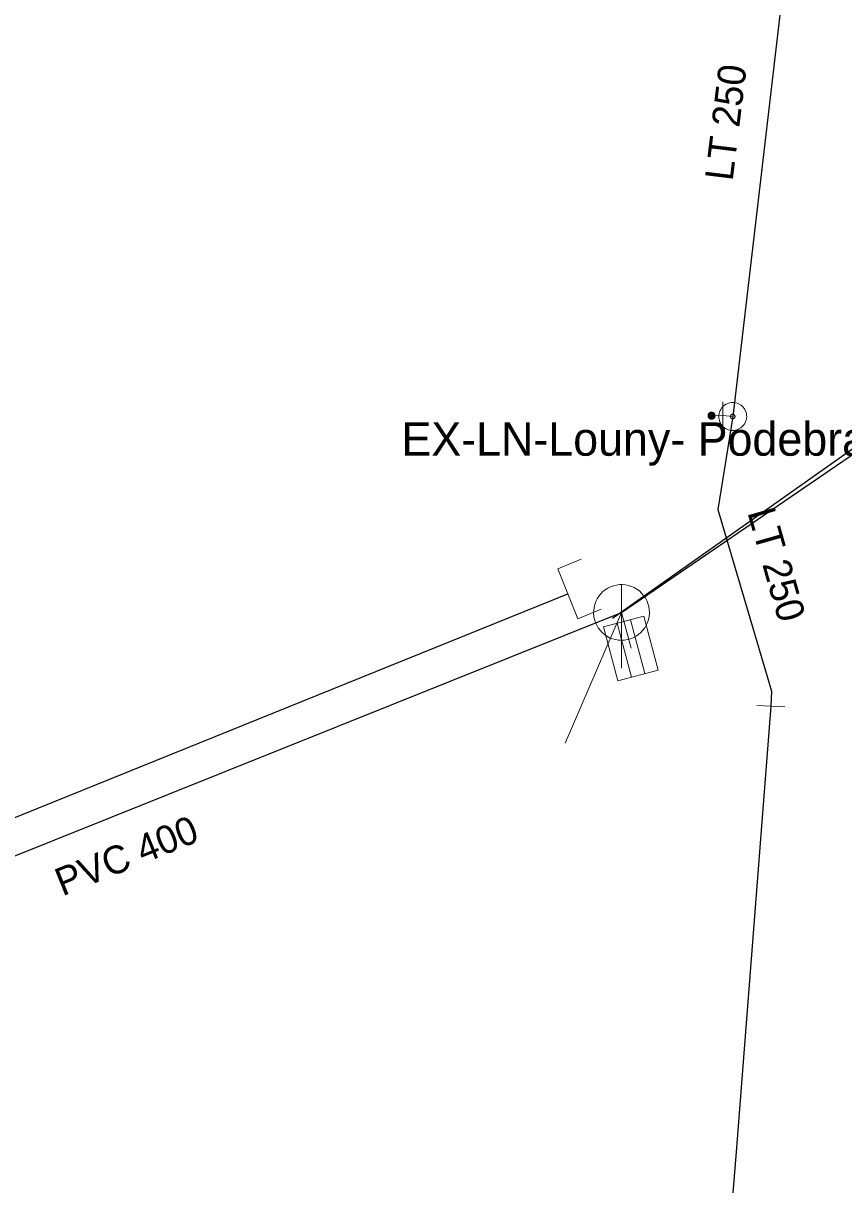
# Model space of a CAD drawing. Extents: x -783064 to -782702, y -1007904 to -1007145.
# Drawn here: x -782854.89 to -782825.5, y -1007838.15 to -1007796.52 of the extents above; entities that cross this region are included whole.
import ezdxf

# ---------------------------------------------------------------- set-up
doc = ezdxf.new("R2010")
doc.units = 0
doc.header["$LTSCALE"] = 0.4
for name, color, linetype, lineweight in [('1', 7, 'Continuous', 13), ('11', 7, 'Continuous', 13), ('14', 7, 'Continuous', 13), ('17', 7, 'Continuous', 25), ('22', 7, 'Continuous', 13), ('34', 7, 'Continuous', 13), ('42', 7, 'Continuous', 13), ('47', 7, 'Continuous', 13), ('9', 7, 'Continuous', 13)]:
    doc.layers.add(name, color=color, linetype=linetype, lineweight=lineweight)

msp = doc.modelspace()

# ---------------------------------------------------------------- linework, layer by layer
at = {"layer": '11'}
for p in [(-782835.48, -1007822.322), (-782833.12, -1007818.92)]:
    msp.add_line(p, (-782833.46, -1007817.64), dxfattribs=at)
at = {"layer": '14', "lineweight": 25}
for p, q in [((-782833.78, -1007817.85), (-782810.509, -1007801.396)), ((-782868.51, -1007831.71), (-782833.46, -1007817.64))]:
    msp.add_line(p, q, dxfattribs=at)
at = {"layer": '14'}
for p, q in [((-782829.833, -1007810.587), (-782830.234, -1007810.588)), ((-782829.476, -1007810.618), (-782829.833, -1007810.587))]:
    msp.add_line(p, q, dxfattribs=at)
at = {"layer": '14', "lineweight": 25}
msp.add_lwpolyline([(-782833.46, -1007817.64), (-782817.57, -1007806.77), (-782809.98, -1007801.58)], dxfattribs=at)
at = {"layer": '17'}
for points in [[(-782826.82, -1007787.241), (-782826.831, -1007787.709), (-782826.833, -1007788.054), (-782829.476, -1007810.618)], [(-782829.476, -1007810.618), (-782830.015, -1007813.952), (-782828.09, -1007820.465), (-782828.114, -1007821.004)], [(-783063.843, -1007879.786), (-783019.96, -1007877.952), (-783013.339, -1007877.559), (-782960.98, -1007867.795), (-782835.384, -1007816.97)], [(-782828.114, -1007821.004), (-782829.348, -1007836.974), (-782830.594, -1007852.256), (-782831.989, -1007872.135), (-782832.224, -1007875.397)]]:
    msp.add_lwpolyline(points, dxfattribs=at)
at = {"layer": '22'}
for p, q in [((-782833.46, -1007819.64), (-782833.459, -1007816.64)), ((-782833.108, -1007819.962), (-782833.621, -1007818.029)), ((-782832.625, -1007819.834), (-782833.138, -1007817.901))]:
    msp.add_line(p, q, dxfattribs=at)
for points in [[(-782832.46, -1007817.64), (-782832.465, -1007817.531), (-782832.483, -1007817.423), (-782832.513, -1007817.317), (-782832.553, -1007817.216), (-782832.605, -1007817.119), (-782832.667, -1007817.029), (-782832.739, -1007816.946), (-782832.819, -1007816.872), (-782832.907, -1007816.806), (-782833.001, -1007816.751), (-782833.101, -1007816.706), (-782833.206, -1007816.673), (-782833.313, -1007816.651), (-782833.422, -1007816.641), (-782833.532, -1007816.643), (-782833.64, -1007816.657), (-782833.747, -1007816.682), (-782833.85, -1007816.719), (-782833.948, -1007816.768), (-782834.04, -1007816.826), (-782834.126, -1007816.895), (-782834.203, -1007816.972), (-782834.272, -1007817.058), (-782834.331, -1007817.15), (-782834.379, -1007817.248), (-782834.416, -1007817.351), (-782834.442, -1007817.458), (-782834.456, -1007817.566), (-782834.459, -1007817.676), (-782834.449, -1007817.785), (-782834.428, -1007817.892), (-782834.394, -1007817.996), (-782834.35, -1007818.096), (-782834.295, -1007818.191), (-782834.229, -1007818.279), (-782834.155, -1007818.359), (-782834.072, -1007818.431), (-782833.982, -1007818.493), (-782833.886, -1007818.545), (-782833.784, -1007818.586), (-782833.679, -1007818.616), (-782833.571, -1007818.634), (-782833.461, -1007818.64), (-782833.352, -1007818.634), (-782833.244, -1007818.616), (-782833.139, -1007818.587), (-782833.037, -1007818.546), (-782832.94, -1007818.494), (-782832.85, -1007818.432), (-782832.767, -1007818.361), (-782832.692, -1007818.281), (-782832.627, -1007818.193), (-782832.571, -1007818.099), (-782832.527, -1007817.999), (-782832.493, -1007817.895), (-782832.471, -1007817.787), (-782832.461, -1007817.678)], [(-782833.591, -1007820.091), (-782834.105, -1007818.158), (-782832.655, -1007817.773), (-782832.141, -1007819.706)]]:
    msp.add_lwpolyline(points, close=True, dxfattribs=at)
at = {"layer": '34'}
for p, q in [((-782829.831, -1007811.086), (-782829.833, -1007810.087)), ((-782827.614, -1007821.025), (-782828.613, -1007820.981))]:
    msp.add_line(p, q, dxfattribs=at)
at = {"layer": '42'}
msp.add_lwpolyline([(-782834.911, -1007815.736), (-782835.746, -1007816.074), (-782835.022, -1007817.865), (-782834.186, -1007817.527)], dxfattribs=at)
at = {"layer": '47'}
for points in [[(-782829.534, -1007811.114), (-782829.482, -1007811.117), (-782829.429, -1007811.115), (-782829.378, -1007811.107), (-782829.327, -1007811.095), (-782829.278, -1007811.077), (-782829.23, -1007811.053), (-782829.187, -1007811.025), (-782829.146, -1007810.992), (-782829.108, -1007810.957), (-782829.075, -1007810.916), (-782829.045, -1007810.872), (-782829.022, -1007810.826), (-782829.002, -1007810.778), (-782828.988, -1007810.727), (-782828.979, -1007810.676), (-782828.976, -1007810.624), (-782828.978, -1007810.571), (-782828.986, -1007810.519), (-782828.998, -1007810.469), (-782829.016, -1007810.42), (-782829.04, -1007810.372), (-782829.068, -1007810.328), (-782829.1, -1007810.287), (-782829.136, -1007810.249), (-782829.177, -1007810.217), (-782829.221, -1007810.187), (-782829.267, -1007810.163), (-782829.315, -1007810.144), (-782829.366, -1007810.13), (-782829.417, -1007810.121), (-782829.469, -1007810.118), (-782829.522, -1007810.12), (-782829.574, -1007810.127), (-782829.624, -1007810.14), (-782829.673, -1007810.158), (-782829.72, -1007810.181), (-782829.765, -1007810.209), (-782829.806, -1007810.241), (-782829.844, -1007810.278), (-782829.876, -1007810.319), (-782829.906, -1007810.363), (-782829.93, -1007810.408), (-782829.949, -1007810.457), (-782829.963, -1007810.508), (-782829.972, -1007810.559), (-782829.975, -1007810.611), (-782829.973, -1007810.664), (-782829.966, -1007810.715), (-782829.953, -1007810.766), (-782829.935, -1007810.815), (-782829.912, -1007810.862), (-782829.884, -1007810.906), (-782829.851, -1007810.947), (-782829.815, -1007810.985), (-782829.774, -1007811.018), (-782829.73, -1007811.048), (-782829.685, -1007811.071), (-782829.636, -1007811.091), (-782829.585, -1007811.105)], [(-782829.485, -1007810.699), (-782829.476, -1007810.7), (-782829.468, -1007810.699), (-782829.46, -1007810.698), (-782829.451, -1007810.696), (-782829.443, -1007810.693), (-782829.436, -1007810.689), (-782829.428, -1007810.684), (-782829.421, -1007810.679), (-782829.416, -1007810.673), (-782829.41, -1007810.666), (-782829.405, -1007810.659), (-782829.401, -1007810.651), (-782829.398, -1007810.644), (-782829.395, -1007810.636), (-782829.394, -1007810.627), (-782829.393, -1007810.618), (-782829.394, -1007810.61), (-782829.395, -1007810.602), (-782829.397, -1007810.593), (-782829.4, -1007810.585), (-782829.404, -1007810.578), (-782829.409, -1007810.57), (-782829.414, -1007810.563), (-782829.42, -1007810.557), (-782829.427, -1007810.552), (-782829.434, -1007810.547), (-782829.442, -1007810.543), (-782829.449, -1007810.54), (-782829.457, -1007810.537), (-782829.466, -1007810.536), (-782829.475, -1007810.535), (-782829.483, -1007810.536), (-782829.491, -1007810.537), (-782829.5, -1007810.539), (-782829.508, -1007810.542), (-782829.515, -1007810.545), (-782829.523, -1007810.551), (-782829.53, -1007810.556), (-782829.536, -1007810.562), (-782829.541, -1007810.569), (-782829.546, -1007810.576), (-782829.55, -1007810.584), (-782829.553, -1007810.591), (-782829.556, -1007810.599), (-782829.557, -1007810.608), (-782829.558, -1007810.617), (-782829.557, -1007810.625), (-782829.556, -1007810.633), (-782829.554, -1007810.642), (-782829.551, -1007810.65), (-782829.548, -1007810.657), (-782829.542, -1007810.665), (-782829.537, -1007810.672), (-782829.531, -1007810.677), (-782829.524, -1007810.683), (-782829.517, -1007810.688), (-782829.509, -1007810.692), (-782829.502, -1007810.695), (-782829.494, -1007810.698)]]:
    msp.add_lwpolyline(points, close=True, dxfattribs=at)
at = {"layer": '9'}
for points in [[(-782830.36, -1007810.588), (-782830.36, -1007810.601), (-782830.358, -1007810.614), (-782830.355, -1007810.627), (-782830.35, -1007810.639), (-782830.344, -1007810.651), (-782830.337, -1007810.662), (-782830.329, -1007810.672), (-782830.319, -1007810.682), (-782830.309, -1007810.69), (-782830.298, -1007810.697), (-782830.286, -1007810.703), (-782830.274, -1007810.708), (-782830.261, -1007810.711), (-782830.248, -1007810.713), (-782830.235, -1007810.715), (-782830.222, -1007810.714), (-782830.209, -1007810.712), (-782830.196, -1007810.709), (-782830.184, -1007810.704), (-782830.172, -1007810.698), (-782830.161, -1007810.691), (-782830.151, -1007810.683), (-782830.141, -1007810.673), (-782830.133, -1007810.663), (-782830.126, -1007810.652), (-782830.12, -1007810.64), (-782830.115, -1007810.628), (-782830.112, -1007810.615), (-782830.11, -1007810.602), (-782830.108, -1007810.589), (-782830.109, -1007810.576), (-782830.111, -1007810.563), (-782830.114, -1007810.55), (-782830.119, -1007810.538), (-782830.125, -1007810.526), (-782830.132, -1007810.515), (-782830.14, -1007810.505), (-782830.15, -1007810.495), (-782830.16, -1007810.487), (-782830.171, -1007810.48), (-782830.183, -1007810.474), (-782830.195, -1007810.469), (-782830.208, -1007810.466), (-782830.221, -1007810.464), (-782830.234, -1007810.463), (-782830.247, -1007810.463), (-782830.26, -1007810.465), (-782830.273, -1007810.468), (-782830.285, -1007810.473), (-782830.297, -1007810.479), (-782830.308, -1007810.486), (-782830.318, -1007810.494), (-782830.328, -1007810.504), (-782830.336, -1007810.514), (-782830.343, -1007810.525), (-782830.349, -1007810.537), (-782830.354, -1007810.549), (-782830.357, -1007810.562), (-782830.359, -1007810.575)], [(-782830.34, -1007810.588), (-782830.341, -1007810.599), (-782830.339, -1007810.61), (-782830.336, -1007810.621), (-782830.332, -1007810.631), (-782830.327, -1007810.641), (-782830.321, -1007810.65), (-782830.314, -1007810.659), (-782830.306, -1007810.667), (-782830.297, -1007810.674), (-782830.288, -1007810.68), (-782830.278, -1007810.685), (-782830.268, -1007810.689), (-782830.257, -1007810.692), (-782830.246, -1007810.695), (-782830.235, -1007810.695), (-782830.224, -1007810.695), (-782830.213, -1007810.693), (-782830.202, -1007810.69), (-782830.192, -1007810.686), (-782830.182, -1007810.681), (-782830.173, -1007810.675), (-782830.164, -1007810.668), (-782830.156, -1007810.66), (-782830.149, -1007810.651), (-782830.143, -1007810.642), (-782830.138, -1007810.632), (-782830.134, -1007810.622), (-782830.131, -1007810.611), (-782830.129, -1007810.6), (-782830.128, -1007810.589), (-782830.128, -1007810.578), (-782830.13, -1007810.567), (-782830.133, -1007810.556), (-782830.137, -1007810.546), (-782830.142, -1007810.536), (-782830.148, -1007810.527), (-782830.155, -1007810.518), (-782830.163, -1007810.51), (-782830.172, -1007810.503), (-782830.181, -1007810.497), (-782830.191, -1007810.492), (-782830.201, -1007810.488), (-782830.212, -1007810.485), (-782830.223, -1007810.483), (-782830.234, -1007810.483), (-782830.245, -1007810.482), (-782830.256, -1007810.484), (-782830.267, -1007810.487), (-782830.277, -1007810.491), (-782830.287, -1007810.496), (-782830.296, -1007810.502), (-782830.305, -1007810.509), (-782830.313, -1007810.517), (-782830.32, -1007810.526), (-782830.326, -1007810.535), (-782830.331, -1007810.545), (-782830.335, -1007810.555), (-782830.338, -1007810.566), (-782830.34, -1007810.577)], [(-782830.321, -1007810.588), (-782830.321, -1007810.597), (-782830.32, -1007810.606), (-782830.317, -1007810.615), (-782830.314, -1007810.623), (-782830.31, -1007810.631), (-782830.305, -1007810.639), (-782830.299, -1007810.646), (-782830.293, -1007810.652), (-782830.286, -1007810.658), (-782830.278, -1007810.663), (-782830.27, -1007810.667), (-782830.262, -1007810.67), (-782830.253, -1007810.673), (-782830.244, -1007810.674), (-782830.235, -1007810.676), (-782830.226, -1007810.675), (-782830.217, -1007810.674), (-782830.208, -1007810.671), (-782830.2, -1007810.668), (-782830.192, -1007810.664), (-782830.184, -1007810.659), (-782830.177, -1007810.653), (-782830.171, -1007810.647), (-782830.165, -1007810.64), (-782830.16, -1007810.632), (-782830.156, -1007810.624), (-782830.153, -1007810.616), (-782830.15, -1007810.607), (-782830.149, -1007810.598), (-782830.147, -1007810.589), (-782830.148, -1007810.58), (-782830.149, -1007810.571), (-782830.152, -1007810.562), (-782830.155, -1007810.554), (-782830.159, -1007810.546), (-782830.164, -1007810.538), (-782830.17, -1007810.531), (-782830.176, -1007810.525), (-782830.183, -1007810.519), (-782830.191, -1007810.514), (-782830.199, -1007810.51), (-782830.207, -1007810.507), (-782830.216, -1007810.504), (-782830.225, -1007810.503), (-782830.234, -1007810.502), (-782830.243, -1007810.502), (-782830.252, -1007810.503), (-782830.261, -1007810.506), (-782830.269, -1007810.509), (-782830.277, -1007810.513), (-782830.285, -1007810.518), (-782830.292, -1007810.524), (-782830.298, -1007810.53), (-782830.304, -1007810.537), (-782830.309, -1007810.545), (-782830.313, -1007810.553), (-782830.316, -1007810.561), (-782830.319, -1007810.57), (-782830.32, -1007810.579)], [(-782830.301, -1007810.588), (-782830.301, -1007810.595), (-782830.3, -1007810.602), (-782830.299, -1007810.609), (-782830.296, -1007810.615), (-782830.293, -1007810.621), (-782830.289, -1007810.627), (-782830.285, -1007810.633), (-782830.28, -1007810.638), (-782830.274, -1007810.642), (-782830.268, -1007810.646), (-782830.262, -1007810.649), (-782830.256, -1007810.652), (-782830.249, -1007810.653), (-782830.242, -1007810.656), (-782830.235, -1007810.656), (-782830.228, -1007810.656), (-782830.221, -1007810.654), (-782830.214, -1007810.653), (-782830.208, -1007810.65), (-782830.201, -1007810.647), (-782830.196, -1007810.643), (-782830.19, -1007810.639), (-782830.185, -1007810.634), (-782830.181, -1007810.628), (-782830.177, -1007810.622), (-782830.174, -1007810.616), (-782830.171, -1007810.61), (-782830.169, -1007810.603), (-782830.168, -1007810.596), (-782830.167, -1007810.589), (-782830.167, -1007810.582), (-782830.168, -1007810.575), (-782830.17, -1007810.568), (-782830.173, -1007810.562), (-782830.176, -1007810.555), (-782830.18, -1007810.55), (-782830.184, -1007810.544), (-782830.189, -1007810.539), (-782830.195, -1007810.535), (-782830.2, -1007810.531), (-782830.207, -1007810.528), (-782830.213, -1007810.525), (-782830.22, -1007810.523), (-782830.227, -1007810.522), (-782830.234, -1007810.522), (-782830.241, -1007810.522), (-782830.248, -1007810.522), (-782830.255, -1007810.524), (-782830.261, -1007810.527), (-782830.267, -1007810.53), (-782830.273, -1007810.534), (-782830.279, -1007810.538), (-782830.284, -1007810.543), (-782830.288, -1007810.549), (-782830.292, -1007810.554), (-782830.295, -1007810.561), (-782830.298, -1007810.567), (-782830.299, -1007810.574), (-782830.301, -1007810.581)], [(-782830.281, -1007810.588), (-782830.281, -1007810.593), (-782830.281, -1007810.598), (-782830.28, -1007810.603), (-782830.278, -1007810.607), (-782830.276, -1007810.612), (-782830.273, -1007810.616), (-782830.27, -1007810.619), (-782830.266, -1007810.623), (-782830.263, -1007810.626), (-782830.259, -1007810.629), (-782830.254, -1007810.631), (-782830.25, -1007810.633), (-782830.245, -1007810.634), (-782830.24, -1007810.636), (-782830.235, -1007810.636), (-782830.23, -1007810.636), (-782830.225, -1007810.635), (-782830.22, -1007810.634), (-782830.216, -1007810.632), (-782830.211, -1007810.63), (-782830.207, -1007810.627), (-782830.203, -1007810.624), (-782830.2, -1007810.62), (-782830.197, -1007810.617), (-782830.194, -1007810.613), (-782830.192, -1007810.608), (-782830.19, -1007810.604), (-782830.189, -1007810.599), (-782830.188, -1007810.594), (-782830.187, -1007810.589), (-782830.187, -1007810.584), (-782830.188, -1007810.579), (-782830.189, -1007810.574), (-782830.191, -1007810.57), (-782830.193, -1007810.565), (-782830.196, -1007810.561), (-782830.199, -1007810.557), (-782830.202, -1007810.554), (-782830.206, -1007810.551), (-782830.21, -1007810.548), (-782830.215, -1007810.546), (-782830.219, -1007810.544), (-782830.224, -1007810.543), (-782830.229, -1007810.542), (-782830.234, -1007810.542), (-782830.239, -1007810.542), (-782830.244, -1007810.543), (-782830.249, -1007810.543), (-782830.253, -1007810.545), (-782830.258, -1007810.547), (-782830.262, -1007810.55), (-782830.265, -1007810.553), (-782830.269, -1007810.556), (-782830.272, -1007810.56), (-782830.275, -1007810.564), (-782830.277, -1007810.569), (-782830.279, -1007810.573), (-782830.28, -1007810.578), (-782830.281, -1007810.583)], [(-782830.261, -1007810.588), (-782830.261, -1007810.591), (-782830.262, -1007810.594), (-782830.261, -1007810.596), (-782830.26, -1007810.599), (-782830.259, -1007810.602), (-782830.257, -1007810.604), (-782830.255, -1007810.606), (-782830.253, -1007810.608), (-782830.251, -1007810.61), (-782830.249, -1007810.612), (-782830.246, -1007810.614), (-782830.243, -1007810.615), (-782830.241, -1007810.615), (-782830.238, -1007810.616), (-782830.235, -1007810.616), (-782830.232, -1007810.616), (-782830.229, -1007810.616), (-782830.226, -1007810.615), (-782830.224, -1007810.614), (-782830.221, -1007810.613), (-782830.219, -1007810.611), (-782830.216, -1007810.609), (-782830.214, -1007810.607), (-782830.213, -1007810.605), (-782830.211, -1007810.603), (-782830.21, -1007810.6), (-782830.208, -1007810.597), (-782830.208, -1007810.595), (-782830.207, -1007810.592), (-782830.206, -1007810.589), (-782830.207, -1007810.586), (-782830.207, -1007810.583), (-782830.208, -1007810.58), (-782830.209, -1007810.578), (-782830.21, -1007810.575), (-782830.212, -1007810.573), (-782830.213, -1007810.57), (-782830.215, -1007810.568), (-782830.218, -1007810.567), (-782830.22, -1007810.565), (-782830.223, -1007810.564), (-782830.225, -1007810.563), (-782830.228, -1007810.562), (-782830.231, -1007810.562), (-782830.234, -1007810.561), (-782830.237, -1007810.562), (-782830.24, -1007810.561), (-782830.242, -1007810.563), (-782830.245, -1007810.563), (-782830.248, -1007810.564), (-782830.25, -1007810.566), (-782830.252, -1007810.567), (-782830.254, -1007810.569), (-782830.256, -1007810.572), (-782830.258, -1007810.574), (-782830.259, -1007810.577), (-782830.26, -1007810.579), (-782830.261, -1007810.582), (-782830.261, -1007810.585)], [(-782830.242, -1007810.588), (-782830.242, -1007810.59), (-782830.242, -1007810.59), (-782830.241, -1007810.59), (-782830.241, -1007810.592), (-782830.242, -1007810.593), (-782830.24, -1007810.593), (-782830.24, -1007810.593), (-782830.24, -1007810.595), (-782830.24, -1007810.595), (-782830.239, -1007810.596), (-782830.237, -1007810.596), (-782830.237, -1007810.596), (-782830.237, -1007810.597), (-782830.235, -1007810.597), (-782830.235, -1007810.597), (-782830.234, -1007810.597), (-782830.233, -1007810.597), (-782830.233, -1007810.596), (-782830.232, -1007810.596), (-782830.23, -1007810.596), (-782830.23, -1007810.595), (-782830.23, -1007810.595), (-782830.229, -1007810.594), (-782830.229, -1007810.594), (-782830.227, -1007810.593), (-782830.227, -1007810.592), (-782830.226, -1007810.591), (-782830.226, -1007810.591), (-782830.226, -1007810.59), (-782830.226, -1007810.589), (-782830.226, -1007810.588), (-782830.226, -1007810.587), (-782830.226, -1007810.587), (-782830.227, -1007810.586), (-782830.227, -1007810.585), (-782830.228, -1007810.584), (-782830.228, -1007810.584), (-782830.229, -1007810.583), (-782830.229, -1007810.583), (-782830.23, -1007810.582), (-782830.231, -1007810.582), (-782830.232, -1007810.581), (-782830.232, -1007810.581), (-782830.233, -1007810.581), (-782830.234, -1007810.581), (-782830.235, -1007810.581), (-782830.236, -1007810.581), (-782830.236, -1007810.581), (-782830.237, -1007810.582), (-782830.238, -1007810.581), (-782830.239, -1007810.583), (-782830.239, -1007810.583), (-782830.24, -1007810.583), (-782830.24, -1007810.583), (-782830.241, -1007810.585), (-782830.241, -1007810.586), (-782830.241, -1007810.587), (-782830.242, -1007810.587), (-782830.242, -1007810.588)]]:
    msp.add_lwpolyline(points, close=True, dxfattribs=at)

# ---------------------------------------------------------------- texts
at = {"layer": '1'}
for s, rotation, p in [('LT 250', 83, (-782829.481, -1007802.2)), ('LT 250', 286, (-782828.957, -1007814.051)), ('PVC 400 ', 22, (-782853.492, -1007827.82))]:
    msp.add_text(s, height=1, rotation=rotation, dxfattribs=at).set_placement(p)
msp.add_text('EX-LN-Louny- Podebradova-04-2020', height=1.2, dxfattribs=at).set_placement((-782841.344, -1007812.023))

doc.saveas('drawing.dxf')
